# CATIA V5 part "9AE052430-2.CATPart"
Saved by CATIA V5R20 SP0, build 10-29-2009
Part number: 9AE052430-2
Revision: ANY
Definition: UNKNOWN
Nomenclature: 9AE052430-2
Source: Unknown
Bounding box of the stored display mesh (mm): x -16.827 to 16.827, y 0 to 44, z -17 to 17
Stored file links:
  C:\Users\Utente\Desktop\IO LAVORO\3D X SITO CF\CUMSA\3D files AE\AE 052430\9AE052430-2.CATPart
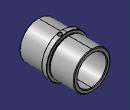
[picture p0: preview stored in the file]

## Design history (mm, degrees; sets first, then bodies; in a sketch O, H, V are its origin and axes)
Body1 "Cortar-Extruir1" (main body)
  Solid1: solid without history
